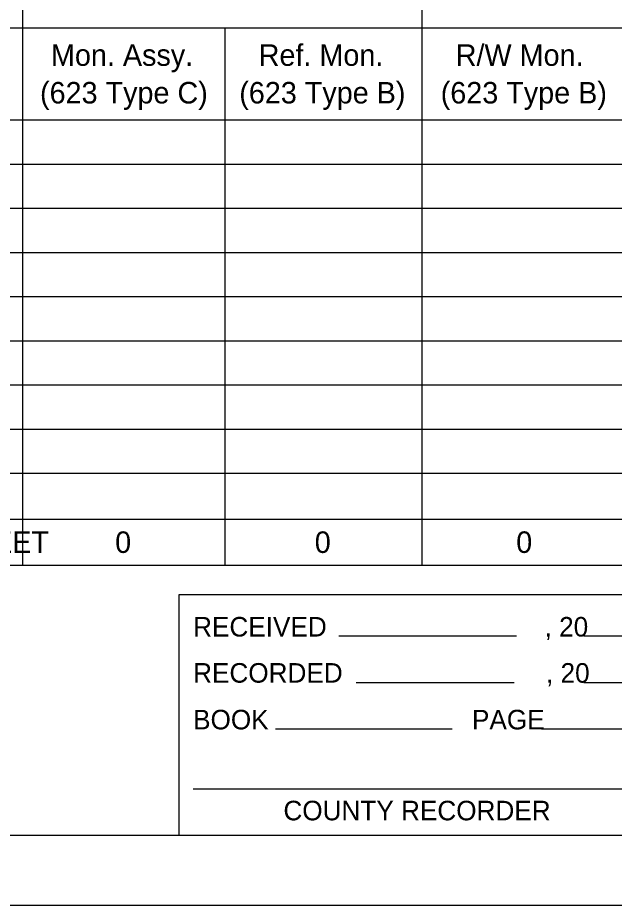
# Model space of a CAD drawing. Extents: x 0 to 34, y 0 to 22.
# Drawn here: x 27.47 to 31.74, y 0 to 6.36 of the extents above; entities that cross this region are included whole.
import ezdxf

# ---------------------------------------------------------------- set-up
doc = ezdxf.new("R2010")
doc.units = 0
for name, color, linetype in [('_CIVIL_CONSTRUCTION', 7, 'Continuous'), ('GE_X_Alignment_100_Bearings', 7, 'Continuous'), ('SG_X_Poles', 7, 'Continuous'), ('SH_Masking', 7, 'Continuous')]:
    doc.layers.add(name, color=color, linetype=linetype)

msp = doc.modelspace()

# ---------------------------------------------------------------- linework, layer by layer
at = {"layer": '_CIVIL_CONSTRUCTION'}
msp.add_lwpolyline([(1.5, 21.5), (33.5, 21.5), (33.5, 0.5), (1.5, 0.5)], close=True, dxfattribs=at)
at = {"layer": 'GE_X_Alignment_100_Bearings'}
for p, q in [((28.6237, 0.5), (28.6237, 2.2242)), ((28.6237, 2.2242), (32, 2.2242)), ((29.7665, 1.9292), (31.039, 1.9292)), ((31.5224, 1.9292), (31.9, 1.9292)), ((29.8919, 1.5958), (31.0229, 1.5958)), ((31.5224, 1.5958), (31.9, 1.5958)), ((29.3131, 1.2625), (30.5791, 1.2625)), ((31.2192, 1.2625), (31.9, 1.2625)), ((28.7237, 0.8343), (31.9, 0.8343))]:
    msp.add_line(p, q, dxfattribs=at)
at = {"layer": 'SG_X_Poles'}
for p, q in [((27.5019, 7.2712), (27.5019, 5.6241)), ((30.3612, 7.2712), (30.3612, 5.6241)), ((17.5404, 6.283), (30.3612, 6.283)), ((28.9513, 6.283), (28.9513, 5.6241)), ((30.3612, 6.283), (31.8369, 6.283)), ((17.5404, 5.6241), (30.3612, 5.6241)), ((27.5019, 5.6241), (27.5019, 4.3592)), ((28.9513, 5.6241), (28.9513, 4.3592)), ((30.3612, 5.6241), (31.8369, 5.6241)), ((30.3612, 5.6241), (30.3612, 4.3592)), ((17.5404, 5.3079), (30.3612, 5.3079)), ((30.3612, 5.3079), (31.8369, 5.3079)), ((17.5404, 4.9917), (30.3612, 4.9917)), ((30.3612, 4.9917), (31.8369, 4.9917)), ((17.5404, 4.6754), (30.3612, 4.6754)), ((30.3612, 4.6754), (31.8369, 4.6754)), ((17.5404, 4.3592), (30.3612, 4.3592)), ((27.5019, 4.3592), (27.5019, 4.043)), ((28.9513, 4.3592), (28.9513, 4.043)), ((30.3612, 4.3592), (31.8369, 4.3592)), ((30.3612, 4.3592), (30.3612, 4.043)), ((17.5404, 4.043), (30.3612, 4.043)), ((27.5019, 4.043), (27.5019, 2.7648)), ((28.9513, 4.043), (28.9513, 2.7648)), ((30.3612, 4.043), (31.8369, 4.043)), ((30.3612, 4.043), (30.3612, 2.7648)), ((17.5404, 3.7267), (30.3612, 3.7267)), ((30.3612, 3.7267), (31.8369, 3.7267)), ((17.5404, 3.4105), (30.3612, 3.4105)), ((30.3612, 3.4105), (31.8369, 3.4105)), ((17.5404, 3.0943), (30.3612, 3.0943)), ((30.3612, 3.0943), (31.8369, 3.0943)), ((17.5404, 2.7648), (27.5019, 2.7648)), ((27.5019, 2.7648), (30.3612, 2.7648)), ((27.5019, 2.7648), (27.5019, 2.4354)), ((28.9513, 2.7648), (28.9513, 2.4354)), ((30.3612, 2.7648), (31.8369, 2.7648)), ((30.3612, 2.7648), (30.3612, 2.4354)), ((17.5404, 2.4354), (30.3612, 2.4354)), ((30.3612, 2.4354), (31.8369, 2.4354))]:
    msp.add_line(p, q, dxfattribs=at)
at = {"layer": 'SH_Masking'}
msp.add_lwpolyline([(0, 0), (34, 0), (34, 22), (0, 22)], close=True, dxfattribs=at)

# ---------------------------------------------------------------- texts
at = {"layer": 'GE_X_Alignment_100_Bearings'}
for s, p in [('RECEIVED                              , 20', (28.7237, 1.9244)), ('RECORDED                            , 20', (28.7237, 1.594)), ('BOOK                            PAGE', (28.7237, 1.2594)), ('COUNTY RECORDER', (29.3705, 0.6082))]:
    msp.add_text(s, height=0.14, dxfattribs=at).set_placement(p)
at = {"layer": 'SG_X_Poles'}
for s, p in [('Mon. Assy.', (27.7056, 6.0113)), ('Ref. Mon.', (29.1935, 6.0113)), ('R/W Mon.', (30.6046, 6.0113)), ('(623 Type C)', (27.6272, 5.7418)), ('(623 Type B)', (29.0542, 5.7418)), ('(623 Type B)', (30.4971, 5.7418)), ('TOTAL CARRIED TO GENERAL SUMMARY SHEET', (22.8051, 2.5231)), ('0', (28.1654, 2.5231)), ('0', (29.595, 2.5231)), ('0', (31.0379, 2.5231))]:
    msp.add_text(s, height=0.154, dxfattribs=at).set_placement(p)

doc.saveas('drawing.dxf')
